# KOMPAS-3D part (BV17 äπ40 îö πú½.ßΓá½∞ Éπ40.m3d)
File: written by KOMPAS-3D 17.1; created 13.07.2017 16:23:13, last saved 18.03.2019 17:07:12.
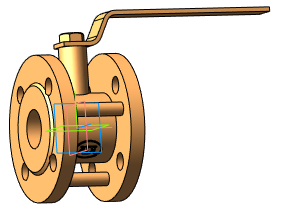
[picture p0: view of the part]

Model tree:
1. Операция без истории:3  (labels: Сталь 20  ГОСТ 1050-88)

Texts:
  DISO1
  DISO2
  BV17 Ду10 ФФ Ру40 угл. сталь
  BV17 Ду15 ФФ Ру40 угл. сталь
  BV17 Ду20 ФФ Ру40 угл. сталь
  BV17 Ду25 ФФ Ру40 угл. сталь
  BV17 Ду32 ФФ Ру40 угл. сталь
  BV17 Ду40 ФФ Ру40 угл. сталь
  BV17 Ду50 ФФ Ру40 угл. сталь
  BV17 Ду65 ФФ Ру40 угл. сталь
  BV17 Ду80 ФФ Ру40 угл. сталь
